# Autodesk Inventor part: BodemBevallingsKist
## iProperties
Created: 2010-03
Part Number: BodemBevallingsKist
Document SubType Name: Modeling
Designer: Ferry
Density: 1 g/cm^3
Author: Ferry
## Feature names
1. Extrusion1
